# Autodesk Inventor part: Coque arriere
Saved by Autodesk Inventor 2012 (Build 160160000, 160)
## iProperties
Created: 2013-08
Part Number: Coque arriere
Material: Default
Document SubType Name: Modeling
Designer: hilarion
Density: 1 g/cm^3
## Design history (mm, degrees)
node "Coque arriere1"
node "Coque arriere"
node "Base1"
